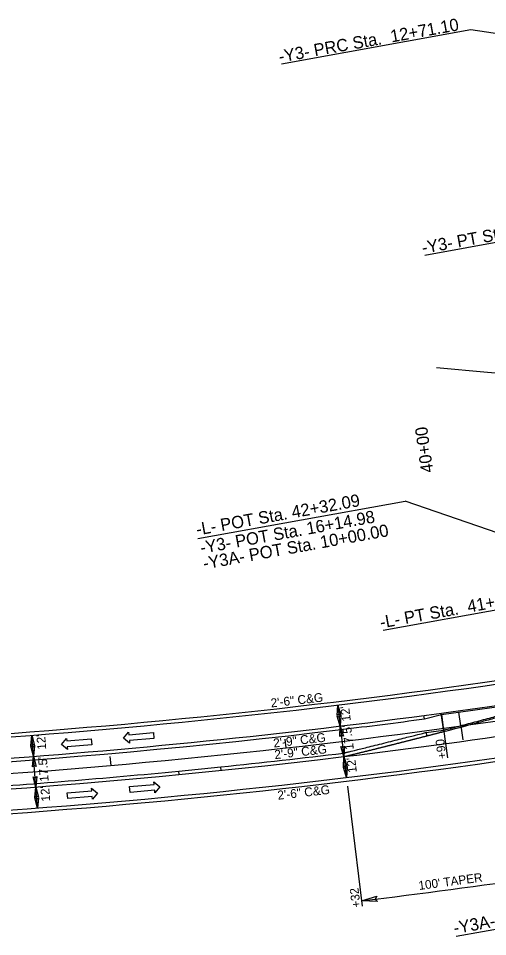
# Model space of a CAD drawing. Extents: x 1616561 to 1622460, y 896726 to 899651.
# Drawn here: x 1620474 to 1620740, y 897959 to 898481 of the extents above; entities that cross this region are included whole.
import ezdxf

# ---------------------------------------------------------------- set-up
doc = ezdxf.new("R2010")
doc.units = 0
for name, color, linetype in [('Exist Boundary Study Area', 7, 'Continuous'), ('Old_Level_3', 7, 'Continuous'), ('Prop Conc 2ft 9in Curb and Gutter', 7, 'Continuous'), ('Prop Dimension', 7, 'Continuous'), ('Prop Horizontal Alignment Tick Small', 7, 'Continuous'), ('Prop Lane Arrow CELL', 7, 'Continuous'), ('Prop Shade Medium', 7, 'Continuous'), ('Prop Superelevation  Arrow CELL', 7, 'Continuous'), ('Prop Superelevation Label', 7, 'Continuous'), ('Prop Terminator CELL', 7, 'Continuous'), ('Sheet Cutting Line CELL', 7, 'Continuous'), ('Sheet North Arrow CELL', 7, 'Continuous')]:
    doc.layers.add(name, color=color, linetype=linetype)

msp = doc.modelspace()

# ---------------------------------------------------------------- linework, layer by layer
at = {"layer": 'Exist Boundary Study Area'}
msp.add_line((1620715.42, 898077.07), (1620714.35, 898084.98), dxfattribs=at)
msp.add_arc((1620177.4, 902041.24), 3992, 277.72898, 280.25995, dxfattribs=at)
msp.add_open_spline([(1620715.49, 898076.55), (1620716.92, 898076.93), (1620722.41, 898078.36), (1620731.96, 898080.87), (1620742.09, 898083.56), (1620749.18, 898085.47), (1620752.22, 898086.29), (1620753.74, 898086.7), (1620754.25, 898086.84), (1620755.26, 898087.11), (1620755.77, 898087.25), (1620756.36, 898087.4)], degree=3, dxfattribs=at)
at = {"layer": 'Old_Level_3'}
for radius, start in [(3991.25, 277.72898), (4008.75, 276.89819)]:
    msp.add_arc((1620177.4, 902041.24), radius, start, 280.25995, dxfattribs=at)
msp.add_open_spline([(1620715.59, 898075.81), (1620722.49, 898077.6), (1620729.29, 898079.39), (1620739.49, 898082.09), (1620742.88, 898083), (1620747.13, 898084.14), (1620747.98, 898084.37), (1620749.68, 898084.83), (1620750.53, 898085.06), (1620751.8, 898085.4), (1620752.44, 898085.57), (1620753.07, 898085.74), (1620753.5, 898085.86), (1620753.71, 898085.91), (1620754.35, 898086.09), (1620754.77, 898086.2), (1620755.62, 898086.43), (1620756.04, 898086.55), (1620756.47, 898086.66)], degree=3, dxfattribs=at)
at = {"layer": 'Prop Conc 2ft 9in Curb and Gutter'}
for radius, start, end in [(3993.25, 276.89819, 277.58549), (3993.25, 270, 276.90062), (4006.75, 275.89522, 276.89819), (4006.75, 273.74663, 275.55203)]:
    msp.add_arc((1620177.4, 902041.24), radius, start, end, dxfattribs=at)
msp.add_open_spline([(1620658.4, 898063.45), (1620658.65, 898063.51), (1620658.91, 898063.58), (1620659.42, 898063.7), (1620659.67, 898063.76), (1620660.44, 898063.95), (1620661.97, 898064.33), (1620665.54, 898065.2), (1620672.68, 898066.96), (1620682.86, 898069.5), (1620693.05, 898072.08), (1620700.17, 898073.89), (1620703.66, 898074.79), (1620705.13, 898075.17), (1620705.57, 898075.28)], degree=3, dxfattribs=at)
at = {"layer": 'Prop Dimension'}
for p, q in [((1620655.33, 898090.8), (1620656.77, 898078.88)), ((1620656.77, 898078.88), (1620658.87, 898061.51)), ((1620482.48, 898061.67), (1620481.57, 898073.63)), ((1620715.42, 898077.07), (1620717.62, 898060.86)), ((1620483.82, 898044.22), (1620482.48, 898061.67)), ((1620658.87, 898061.51), (1620660.31, 898049.6)), ((1620484.74, 898032.25), (1620483.82, 898044.22)), ((1620660.92, 898044.63), (1620669.16, 897976.52))]:
    msp.add_line(p, q, dxfattribs=at)
msp.add_arc((1620176.16, 902049.2), 4099.41, 276.90211, 278.33169, dxfattribs=at)
at = {"layer": 'Prop Horizontal Alignment Tick Small'}
for p, q in [((1620704.53, 898082.94), (1620704.26, 898084.9)), ((1620704.53, 898082.94), (1620714.27, 898085.51)), ((1620705.57, 898075.28), (1620715.49, 898076.55)), ((1620706.07, 898073.34), (1620705.57, 898075.28)), ((1620565.05, 898053.29), (1620588.93, 898055.68)), ((1620565.25, 898051.3), (1620565.05, 898053.29)), ((1620589.13, 898053.69), (1620588.93, 898055.68))]:
    msp.add_line(p, q, dxfattribs=at)
for radius, end in [(3977.25, 279.98877), (4022.75, 280.19565)]:
    msp.add_arc((1620177.4, 902041.24), radius, 270, end, dxfattribs=at)
at = {"layer": 'Prop Lane Arrow CELL'}
for p, q in [((1620533.68, 898071.92), (1620536.53, 898075.39)), ((1620536.53, 898075.39), (1620536.67, 898073.89)), ((1620536.67, 898073.89), (1620550.61, 898075.15)), ((1620550.61, 898075.15), (1620550.91, 898071.86)), ((1620498.39, 898068.43), (1620501.25, 898071.89)), ((1620501.79, 898065.61), (1620498.39, 898068.43)), ((1620501.25, 898071.89), (1620501.38, 898070.4)), ((1620501.38, 898070.4), (1620515.33, 898071.58)), ((1620515.61, 898068.3), (1620501.66, 898067.11)), ((1620501.66, 898067.11), (1620501.79, 898065.61)), ((1620515.33, 898071.58), (1620515.61, 898068.3)), ((1620537.1, 898069.11), (1620533.68, 898071.92)), ((1620550.91, 898071.86), (1620536.96, 898070.61)), ((1620536.96, 898070.61), (1620537.1, 898069.11)), ((1620551.05, 898045.7), (1620550.91, 898047.2)), ((1620550.91, 898047.2), (1620554.33, 898044.39)), ((1620501.67, 898040.95), (1620515.62, 898042.14)), ((1620501.95, 898037.66), (1620501.67, 898040.95)), ((1620515.62, 898042.14), (1620515.5, 898043.63)), ((1620515.5, 898043.63), (1620518.9, 898040.81)), ((1620537.1, 898044.45), (1620551.05, 898045.7)), ((1620537.4, 898041.16), (1620537.1, 898044.45)), ((1620551.34, 898042.42), (1620537.4, 898041.16)), ((1620551.48, 898040.92), (1620551.34, 898042.42)), ((1620554.33, 898044.39), (1620551.48, 898040.92)), ((1620515.9, 898038.85), (1620501.95, 898037.66)), ((1620516.03, 898037.35), (1620515.9, 898038.85)), ((1620518.9, 898040.81), (1620516.03, 898037.35))]:
    msp.add_line(p, q, dxfattribs=at)
at = {"layer": 'Prop Shade Medium'}
msp.add_line((1620714.27, 898085.51), (1620715.49, 898076.55), dxfattribs=at)
msp.add_arc((1620177.4, 902041.24), 3992, 277.72898, 280.25995, dxfattribs=at)
msp.add_open_spline([(1620715.49, 898076.55), (1620716.92, 898076.93), (1620722.41, 898078.36), (1620731.96, 898080.87), (1620742.09, 898083.56), (1620749.18, 898085.47), (1620752.22, 898086.29), (1620753.74, 898086.7), (1620754.25, 898086.84), (1620755.26, 898087.11), (1620755.77, 898087.25), (1620756.36, 898087.4)], degree=3, dxfattribs=at)
at = {"layer": 'Prop Superelevation  Arrow CELL'}
for p, q in [((1620626.04, 898066.48), (1620625.48, 898071.45)), ((1620526.54, 898056.51), (1620526.1, 898061.49))]:
    msp.add_line(p, q, dxfattribs=at)
at = {"layer": 'Prop Superelevation Label'}
for q in [(1620724.16, 898086.86), (1620726.35, 898071.01)]:
    msp.add_line((1620725.26, 898078.94), q, dxfattribs=at)
at = {"layer": 'Prop Terminator CELL'}
msp.add_line((1620715.59, 898075.81), (1620714.17, 898086.25), dxfattribs=at)
for points in [[(1620655.03, 898084.87), (1620655.33, 898090.8), (1620657.07, 898085.08), (1620655.95, 898085.7)], [(1620657.07, 898084.81), (1620656.77, 898078.88), (1620655.03, 898084.6), (1620656.16, 898083.98)], [(1620656.47, 898072.95), (1620656.77, 898078.88), (1620658.51, 898073.17), (1620657.39, 898073.78)], [(1620481.01, 898067.72), (1620481.57, 898073.63), (1620483.05, 898067.85), (1620481.96, 898068.51)], [(1620483.04, 898067.58), (1620482.48, 898061.67), (1620481, 898067.45), (1620482.09, 898066.79)], [(1620659.17, 898067.44), (1620658.87, 898061.51), (1620657.13, 898067.22), (1620658.26, 898066.61)], [(1620481.93, 898055.76), (1620482.48, 898061.67), (1620483.97, 898055.88), (1620482.88, 898056.55)], [(1620658.58, 898055.58), (1620658.87, 898061.51), (1620660.61, 898055.79), (1620659.49, 898056.41)], [(1620660.61, 898055.52), (1620660.31, 898049.6), (1620658.58, 898055.31), (1620659.7, 898054.69)], [(1620484.38, 898050.13), (1620483.82, 898044.22), (1620482.33, 898050), (1620483.43, 898049.34)], [(1620483.26, 898038.31), (1620483.82, 898044.22), (1620485.31, 898038.43), (1620484.21, 898039.1)], [(1620485.29, 898038.16), (1620484.74, 898032.25), (1620483.25, 898038.04), (1620484.34, 898037.37)], [(1620677.92, 897979.04), (1620668.8, 897979.5), (1620677.59, 897982.17), (1620676.64, 897980.45)]]:
    msp.add_lwpolyline(points, close=True, dxfattribs=at)
for radius, end in [(3979.25, 279.98877), (3991.25, 277.72898), (4020.75, 280.19565), (4008.75, 276.89819)]:
    msp.add_arc((1620177.4, 902041.24), radius, 270, end, dxfattribs=at)
for points in [[(1620658.87, 898061.51), (1620659.54, 898061.67), (1620660.2, 898061.83), (1620660.86, 898062), (1620661.52, 898062.16), (1620662.19, 898062.32), (1620662.85, 898062.48), (1620663.51, 898062.64), (1620664.17, 898062.81), (1620664.83, 898062.97), (1620665.5, 898063.13), (1620666.16, 898063.3), (1620666.82, 898063.46), (1620667.48, 898063.62), (1620668.14, 898063.79), (1620668.81, 898063.95), (1620669.47, 898064.11), (1620670.13, 898064.28), (1620670.79, 898064.44), (1620671.45, 898064.6), (1620672.12, 898064.77), (1620672.78, 898064.93), (1620673.44, 898065.1), (1620674.1, 898065.26), (1620674.76, 898065.42), (1620675.42, 898065.59), (1620676.09, 898065.75), (1620676.75, 898065.92), (1620677.41, 898066.08), (1620678.07, 898066.25), (1620678.73, 898066.41), (1620679.39, 898066.58), (1620680.05, 898066.74), (1620680.71, 898066.91), (1620681.38, 898067.08), (1620682.04, 898067.24), (1620682.7, 898067.41), (1620683.36, 898067.57), (1620684.02, 898067.74), (1620684.68, 898067.9), (1620685.34, 898068.07), (1620686, 898068.24), (1620686.66, 898068.4), (1620687.32, 898068.57), (1620687.98, 898068.74), (1620688.65, 898068.9), (1620689.31, 898069.07), (1620689.97, 898069.24), (1620690.63, 898069.4), (1620691.29, 898069.57), (1620691.95, 898069.74), (1620692.61, 898069.91), (1620693.27, 898070.07), (1620693.93, 898070.24), (1620694.59, 898070.41), (1620695.25, 898070.58), (1620695.91, 898070.74), (1620696.57, 898070.91), (1620697.23, 898071.08), (1620697.89, 898071.25), (1620698.55, 898071.42), (1620699.21, 898071.59), (1620699.87, 898071.75), (1620700.53, 898071.92), (1620701.19, 898072.09), (1620701.85, 898072.26), (1620702.51, 898072.43), (1620703.17, 898072.6), (1620703.83, 898072.77), (1620704.49, 898072.94), (1620705.15, 898073.11), (1620705.81, 898073.28), (1620706.47, 898073.45), (1620707.13, 898073.62), (1620707.79, 898073.79)], [(1620658.87, 898061.51), (1620659.54, 898061.67), (1620660.2, 898061.83), (1620660.86, 898062), (1620661.52, 898062.16), (1620662.19, 898062.32), (1620662.85, 898062.48), (1620663.51, 898062.64), (1620664.17, 898062.81), (1620664.83, 898062.97), (1620665.5, 898063.13), (1620666.16, 898063.3), (1620666.82, 898063.46), (1620667.48, 898063.62), (1620668.14, 898063.79), (1620668.81, 898063.95), (1620669.47, 898064.11), (1620670.13, 898064.28), (1620670.79, 898064.44), (1620671.45, 898064.6), (1620672.12, 898064.77), (1620672.78, 898064.93), (1620673.44, 898065.1), (1620674.1, 898065.26), (1620674.76, 898065.42), (1620675.42, 898065.59), (1620676.09, 898065.75), (1620676.75, 898065.92), (1620677.41, 898066.08), (1620678.07, 898066.25), (1620678.73, 898066.41), (1620679.39, 898066.58), (1620680.05, 898066.74), (1620680.71, 898066.91), (1620681.38, 898067.08), (1620682.04, 898067.24), (1620682.7, 898067.41), (1620683.36, 898067.57), (1620684.02, 898067.74), (1620684.68, 898067.9), (1620685.34, 898068.07), (1620686, 898068.24), (1620686.66, 898068.4), (1620687.32, 898068.57), (1620687.98, 898068.74), (1620688.65, 898068.9), (1620689.31, 898069.07), (1620689.97, 898069.24), (1620690.63, 898069.4), (1620691.29, 898069.57), (1620691.95, 898069.74), (1620692.61, 898069.91), (1620693.27, 898070.07), (1620693.93, 898070.24), (1620694.59, 898070.41), (1620695.25, 898070.58), (1620695.91, 898070.74), (1620696.57, 898070.91), (1620697.23, 898071.08), (1620697.89, 898071.25), (1620698.55, 898071.42), (1620699.21, 898071.59), (1620699.87, 898071.75), (1620700.53, 898071.92), (1620701.19, 898072.09), (1620701.85, 898072.26), (1620702.51, 898072.43), (1620703.17, 898072.6), (1620703.83, 898072.77), (1620704.49, 898072.94), (1620705.15, 898073.11), (1620705.81, 898073.28), (1620706.47, 898073.45), (1620707.13, 898073.62), (1620707.79, 898073.79)], [(1620707.79, 898073.79), (1620708.45, 898073.96), (1620709.11, 898074.13), (1620709.76, 898074.3), (1620710.42, 898074.47), (1620711.08, 898074.64), (1620711.74, 898074.81), (1620712.4, 898074.98), (1620713.06, 898075.15), (1620713.72, 898075.32), (1620714.38, 898075.49), (1620715.04, 898075.66), (1620715.59, 898075.81)], [(1620707.79, 898073.79), (1620708.45, 898073.96), (1620709.11, 898074.13), (1620709.76, 898074.3), (1620710.42, 898074.47), (1620711.08, 898074.64), (1620711.74, 898074.81), (1620712.4, 898074.98), (1620713.06, 898075.15), (1620713.72, 898075.32), (1620714.38, 898075.49), (1620715.04, 898075.66), (1620715.59, 898075.81)]]:
    msp.add_spline(points, degree=3, dxfattribs=at)
at = {"layer": 'Sheet Cutting Line CELL'}
msp.add_line((1620711.49, 898282.79), (1620740.47, 898280.19), dxfattribs=at)
for centre, radius, start, end in [((1620776.25, 898678.58), 400, 264.8669, 270), ((1620177.4, 902041.24), 4000, 270, 280.25995)]:
    msp.add_arc(centre, radius, start, end, dxfattribs=at)
at = {"layer": 'Sheet North Arrow CELL'}
for p, q in [((1620730.97, 898474.73), (1620623.29, 898455.24)), ((1620885.24, 898452.5), (1620730.97, 898474.73)), ((1620810.13, 898365.53), (1620704.88, 898346.47)), ((1620575.78, 898185.51), (1620693.65, 898206.85)), ((1620954.2, 898116.85), (1620693.65, 898206.85)), ((1620781.47, 898151.37), (1620681.08, 898133.2)), ((1620834.98, 897979.47), (1620722.68, 897959.15))]:
    msp.add_line(p, q, dxfattribs=at)

# ---------------------------------------------------------------- texts
at = {"layer": 'Prop Dimension'}
for s, height, rotation, p in [('40+00', 7, 97.8722, (1620709.66, 898223.41)), ('2\'-6" C&G', 5.044, 6.5187, (1620617.53, 898089.44)), ("12'", 5, 96.8982, (1620662.77, 898081.83)), ("17.5'", 5, 96.8982, (1620664.5, 898065.65)), ("12'", 5, 94.4673, (1620489.74, 898065.62)), ('2\'-9" C&G', 5.044, 6.5187, (1620619.01, 898066.65)), ('2\'-9" C&G', 5.044, 6.5187, (1620619.64, 898060.06)), ('+90', 5, 97.729, (1620717.22, 898060.55)), ("17.5'", 5, 94.4673, (1620491.14, 898047.43)), ("12'", 5, 96.8982, (1620666.22, 898052.6)), ("12'", 5, 94.4673, (1620492, 898036.2)), ('2\'-6" C&G', 5.044, 6.5187, (1620621.38, 898036.97)), ("100' TAPER", 5, 7.6031, (1620701.54, 897985.65)), ('+32', 5, 96.9006, (1620668.37, 897975.91))]:
    msp.add_text(s, height=height, rotation=rotation, dxfattribs=at).set_placement(p)
at = {"layer": 'Sheet North Arrow CELL'}
for s, p in [('-Y3- PRC Sta.  12+71.10', (1620622.42, 898456.07)), ('-Y3- PT Sta.  14+15.72', (1620703.71, 898347.37)), ('-L- POT Sta. 42+32.09', (1620575.5, 898187.2)), ('-Y3- POT Sta. 16+14.98', (1620577.82, 898176.77)), ('-Y3A- POT Sta. 10+00.00', (1620579.45, 898167.88)), ('-L- PT Sta.  41+66.70', (1620679.92, 898134.37)), ('-Y3A- PC Sta.  10+49.80', (1620721.72, 897960.55))]:
    msp.add_text(s, height=7, rotation=10.2599, dxfattribs=at).set_placement(p)

doc.saveas('drawing.dxf')
